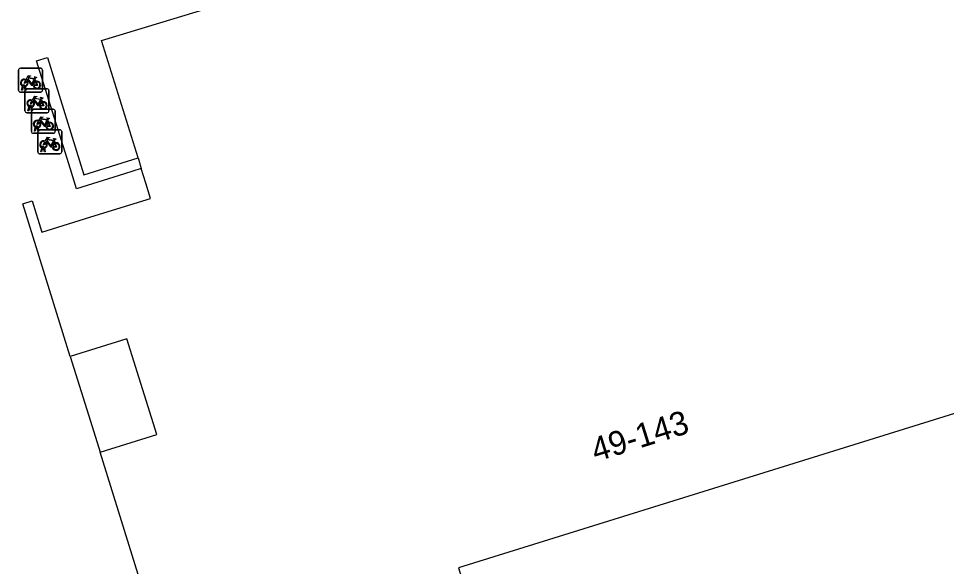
# Model space of a CAD drawing. Extents: x 161354 to 161876, y 382161 to 382804.
# Drawn here: x 161790.51 to 161829.3, y 382336.2 to 382359.11 of the extents above; entities that cross this region are included whole.
import ezdxf

# ---------------------------------------------------------------- set-up
doc = ezdxf.new("R2010")
doc.units = 0
for name, color, linetype in [('IMGEO_Fietsenrek', 7, 'Continuous'), ('IMGEO_Muur', 7, 'Continuous'), ('IMGEO_Pand', 7, 'Continuous'), ('IMGEO_Pand_nummerreeks', 7, 'Continuous'), ('IMGEO_Pand_overbouw', 7, 'Continuous')]:
    doc.layers.add(name, color=color, linetype=linetype)

msp = doc.modelspace()

# ---------------------------------------------------------------- linework, layer by layer
at = {"layer": 'IMGEO_Fietsenrek'}
for p, q in [((161790.507, 382356.108), (161790.507, 382356.949)), ((161790.507, 382356.949), (161790.507, 382356.108)), ((161790.582, 382357.033), (161791.423, 382357.033)), ((161791.423, 382357.033), (161790.582, 382357.033)), ((161791.507, 382356.958), (161791.507, 382356.117)), ((161791.507, 382356.117), (161791.507, 382356.958)), ((161791.194, 382356.582), (161791.23, 382356.487)), ((161790.634, 382356.117), (161790.673, 382356.277)), ((161790.668, 382356.117), (161790.634, 382356.117)), ((161790.703, 382356.265), (161790.668, 382356.117)), ((161790.745, 382356.289), (161790.744, 382356.293)), ((161790.786, 382356.117), (161790.752, 382356.259)), ((161790.776, 382356.3), (161790.777, 382356.293)), ((161790.784, 382356.263), (161790.819, 382356.117)), ((161790.819, 382356.117), (161790.786, 382356.117)), ((161790.85, 382356.174), (161791.691, 382356.174)), ((161791.691, 382356.174), (161790.85, 382356.174)), ((161791.432, 382356.033), (161790.591, 382356.033)), ((161790.591, 382356.033), (161791.432, 382356.033)), ((161790.775, 382355.249), (161790.775, 382356.09)), ((161790.775, 382356.09), (161790.775, 382355.249)), ((161791.775, 382356.099), (161791.775, 382355.258)), ((161791.775, 382355.258), (161791.775, 382356.099)), ((161790.902, 382355.258), (161790.941, 382355.418)), ((161790.971, 382355.406), (161790.936, 382355.258)), ((161791.013, 382355.43), (161791.012, 382355.434)), ((161791.054, 382355.258), (161791.02, 382355.4)), ((161791.044, 382355.441), (161791.045, 382355.434)), ((161791.052, 382355.404), (161791.087, 382355.258)), ((161791.462, 382355.723), (161791.498, 382355.628)), ((161791.7, 382355.174), (161790.859, 382355.174)), ((161790.859, 382355.174), (161791.7, 382355.174)), ((161790.936, 382355.258), (161790.902, 382355.258)), ((161791.042, 382354.389), (161791.042, 382355.23)), ((161791.042, 382355.23), (161791.042, 382354.389)), ((161791.087, 382355.258), (161791.054, 382355.258)), ((161791.117, 382355.314), (161791.958, 382355.314)), ((161791.958, 382355.314), (161791.117, 382355.314)), ((161792.042, 382355.239), (161792.042, 382354.398)), ((161792.042, 382354.398), (161792.042, 382355.239)), ((161791.28, 382354.57), (161791.279, 382354.574)), ((161791.311, 382354.581), (161791.312, 382354.574)), ((161791.729, 382354.863), (161791.765, 382354.768)), ((161791.967, 382354.314), (161791.126, 382354.314)), ((161791.126, 382354.314), (161791.967, 382354.314)), ((161791.169, 382354.398), (161791.208, 382354.558)), ((161791.203, 382354.398), (161791.169, 382354.398)), ((161791.238, 382354.546), (161791.203, 382354.398)), ((161791.321, 382354.398), (161791.287, 382354.54)), ((161791.31, 382353.53), (161791.31, 382354.371)), ((161791.31, 382354.371), (161791.31, 382353.53)), ((161791.319, 382354.544), (161791.354, 382354.398)), ((161791.354, 382354.398), (161791.321, 382354.398)), ((161791.385, 382354.455), (161792.226, 382354.455)), ((161792.226, 382354.455), (161791.385, 382354.455)), ((161792.31, 382354.38), (161792.31, 382353.539)), ((161792.31, 382353.539), (161792.31, 382354.38)), ((161791.997, 382354.004), (161792.033, 382353.909)), ((161792.235, 382353.455), (161791.394, 382353.455)), ((161791.394, 382353.455), (161792.235, 382353.455)), ((161791.437, 382353.539), (161791.476, 382353.699)), ((161791.471, 382353.539), (161791.437, 382353.539)), ((161791.506, 382353.687), (161791.471, 382353.539)), ((161791.548, 382353.711), (161791.547, 382353.715)), ((161791.589, 382353.539), (161791.555, 382353.681)), ((161791.579, 382353.722), (161791.58, 382353.715)), ((161791.587, 382353.685), (161791.622, 382353.539)), ((161791.622, 382353.539), (161791.589, 382353.539))]:
    msp.add_line(p, q, dxfattribs=at)
for points in [[(161790.841, 382356.507), (161790.789, 382356.417), (161790.749, 382356.392), (161790.75, 382356.439), (161790.805, 382356.533)], [(161790.82, 382356.559), (161790.915, 382356.723), (161791.001, 382356.709), (161791.003, 382356.7), (161790.947, 382356.689), (161790.92, 382356.644), (161791.176, 382356.603)], [(161791.116, 382356.315), (161791.066, 382356.315), (161790.875, 382356.566), (161790.856, 382356.534)], [(161791.163, 382356.578), (161790.906, 382356.619), (161790.889, 382356.59), (161791.056, 382356.37), (161791.163, 382356.578)], [(161791.211, 382356.48), (161791.181, 382356.557), (161791.072, 382356.339), (161791.115, 382356.339)], [(161791.176, 382356.603), (161791.201, 382356.652), (161791.195, 382356.656), (161791.172, 382356.66), (161791.16, 382356.667), (161791.159, 382356.67), (161791.161, 382356.675), (161791.256, 382356.66), (161791.258, 382356.65), (161791.248, 382356.637), (161791.236, 382356.631), (161791.222, 382356.637), (161791.194, 382356.582)], [(161791.145, 382356.339), (161791.265, 382356.338), (161791.221, 382356.452)], [(161791.241, 382356.459), (161791.296, 382356.314), (161791.146, 382356.314)], [(161791.088, 382355.7), (161791.183, 382355.864), (161791.269, 382355.85), (161791.271, 382355.841), (161791.215, 382355.83), (161791.188, 382355.785), (161791.444, 382355.744)], [(161791.431, 382355.719), (161791.174, 382355.76), (161791.157, 382355.731), (161791.324, 382355.511), (161791.431, 382355.719)], [(161791.444, 382355.744), (161791.469, 382355.793), (161791.463, 382355.797), (161791.44, 382355.801), (161791.428, 382355.808), (161791.427, 382355.811), (161791.429, 382355.816), (161791.524, 382355.801), (161791.526, 382355.791), (161791.516, 382355.778), (161791.504, 382355.772), (161791.49, 382355.778), (161791.462, 382355.723)], [(161791.109, 382355.648), (161791.057, 382355.558), (161791.017, 382355.533), (161791.018, 382355.58), (161791.073, 382355.674)], [(161791.384, 382355.456), (161791.334, 382355.456), (161791.143, 382355.707), (161791.124, 382355.675)], [(161791.479, 382355.621), (161791.449, 382355.698), (161791.34, 382355.48), (161791.383, 382355.48)], [(161791.413, 382355.48), (161791.533, 382355.479), (161791.489, 382355.593)], [(161791.509, 382355.6), (161791.564, 382355.455), (161791.414, 382355.455)], [(161791.355, 382354.84), (161791.45, 382355.004), (161791.536, 382354.99), (161791.538, 382354.981), (161791.482, 382354.97), (161791.455, 382354.925), (161791.711, 382354.884)], [(161791.711, 382354.884), (161791.736, 382354.933), (161791.73, 382354.937), (161791.707, 382354.941), (161791.695, 382354.948), (161791.694, 382354.951), (161791.696, 382354.956), (161791.791, 382354.941), (161791.793, 382354.931), (161791.783, 382354.918), (161791.771, 382354.912), (161791.757, 382354.918), (161791.729, 382354.863)], [(161791.376, 382354.788), (161791.324, 382354.698), (161791.284, 382354.673), (161791.285, 382354.72), (161791.34, 382354.814)], [(161791.651, 382354.596), (161791.601, 382354.596), (161791.41, 382354.847), (161791.391, 382354.815)], [(161791.698, 382354.859), (161791.441, 382354.9), (161791.424, 382354.871), (161791.591, 382354.651), (161791.698, 382354.859)], [(161791.746, 382354.761), (161791.716, 382354.838), (161791.607, 382354.62), (161791.65, 382354.62)], [(161791.68, 382354.62), (161791.8, 382354.619), (161791.756, 382354.733)], [(161791.776, 382354.74), (161791.831, 382354.595), (161791.681, 382354.595)], [(161791.644, 382353.929), (161791.592, 382353.839), (161791.552, 382353.814), (161791.553, 382353.861), (161791.608, 382353.955)], [(161791.623, 382353.981), (161791.718, 382354.145), (161791.804, 382354.131), (161791.806, 382354.122), (161791.75, 382354.111), (161791.723, 382354.066), (161791.979, 382354.025)], [(161791.919, 382353.737), (161791.869, 382353.737), (161791.678, 382353.988), (161791.659, 382353.956)], [(161791.966, 382354), (161791.709, 382354.041), (161791.692, 382354.012), (161791.859, 382353.792), (161791.966, 382354)], [(161792.014, 382353.902), (161791.984, 382353.979), (161791.875, 382353.761), (161791.918, 382353.761)], [(161791.948, 382353.761), (161792.068, 382353.76), (161792.024, 382353.874)], [(161792.044, 382353.881), (161792.099, 382353.736), (161791.949, 382353.736)], [(161791.979, 382354.025), (161792.004, 382354.074), (161791.998, 382354.078), (161791.975, 382354.082), (161791.963, 382354.089), (161791.962, 382354.092), (161791.964, 382354.097), (161792.059, 382354.082), (161792.061, 382354.072), (161792.051, 382354.059), (161792.039, 382354.053), (161792.025, 382354.059), (161791.997, 382354.004)]]:
    msp.add_lwpolyline(points, dxfattribs=at)
for centre, radius, start, end in [((161790.585, 382356.955), 0.0779, 92.4484, 184.2845), ((161790.585, 382356.955), 0.0779, 92.4484, 184.2845), ((161791.429, 382356.955), 0.0779, 2.4484, 94.2845), ((161791.429, 382356.955), 0.0779, 2.4484, 94.2845), ((161790.747, 382356.418), 0.159, 62.6766, 242.1369), ((161790.747, 382356.418), 0.129, 63.3192, 238.903), ((161790.747, 382356.418), 0.129, 283.6043, 43.4302), ((161790.747, 382356.418), 0.159, 283.5766, 46.6042), ((161790.727, 382356.289), 0.0499, 12.8025, 158.6934), ((161790.747, 382356.418), 0.159, 253.9967, 271.7867), ((161790.727, 382356.289), 0.0174, 12.8025, 163.4502), ((161790.747, 382356.418), 0.129, 253.415, 269.0204), ((161790.853, 382356.096), 0.0779, 92.4484, 184.2845), ((161790.853, 382356.096), 0.0779, 92.4484, 184.2845), ((161791.274, 382356.334), 0.159, 113.3408, 178.3217), ((161791.274, 382356.334), 0.159, 187.0065, 105.7708), ((161791.274, 382356.334), 0.129, 113.923, 177.9556), ((161791.274, 382356.334), 0.129, 188.6715, 104.5883), ((161791.429, 382356.111), 0.0779, 272.4484, 4.2845), ((161791.429, 382356.111), 0.0779, 272.4484, 4.2845), ((161791.697, 382356.096), 0.0779, 2.4484, 94.2845), ((161791.697, 382356.096), 0.0779, 2.4484, 94.2845), ((161790.585, 382356.111), 0.0779, 182.4484, 274.2845), ((161790.585, 382356.111), 0.0779, 182.4484, 274.2845), ((161791.015, 382355.559), 0.159, 62.6766, 242.1369), ((161791.015, 382355.559), 0.129, 63.3192, 238.903), ((161790.995, 382355.43), 0.0499, 12.8025, 158.6934), ((161791.015, 382355.559), 0.159, 253.9967, 271.7867), ((161790.995, 382355.43), 0.0174, 12.8025, 163.4502), ((161791.015, 382355.559), 0.129, 253.415, 269.0204), ((161791.015, 382355.559), 0.129, 283.6043, 43.4302), ((161791.015, 382355.559), 0.159, 283.5766, 46.6042), ((161791.542, 382355.475), 0.159, 113.3408, 178.3217), ((161791.542, 382355.475), 0.159, 187.0065, 105.7708), ((161791.542, 382355.475), 0.129, 113.923, 177.9556), ((161791.542, 382355.475), 0.129, 188.6715, 104.5883), ((161790.853, 382355.252), 0.0779, 182.4484, 274.2845), ((161790.853, 382355.252), 0.0779, 182.4484, 274.2845), ((161791.12, 382355.236), 0.0779, 92.4484, 184.2845), ((161791.12, 382355.236), 0.0779, 92.4484, 184.2845), ((161791.697, 382355.252), 0.0779, 272.4484, 4.2845), ((161791.697, 382355.252), 0.0779, 272.4484, 4.2845), ((161791.964, 382355.236), 0.0779, 2.4484, 94.2845), ((161791.964, 382355.236), 0.0779, 2.4484, 94.2845), ((161791.282, 382354.699), 0.159, 62.6766, 242.1369), ((161791.282, 382354.699), 0.129, 63.3192, 238.903), ((161791.262, 382354.57), 0.0499, 12.8025, 158.6934), ((161791.262, 382354.57), 0.0174, 12.8025, 163.4502), ((161791.282, 382354.699), 0.129, 253.415, 269.0204), ((161791.282, 382354.699), 0.129, 283.6043, 43.4302), ((161791.282, 382354.699), 0.159, 283.5766, 46.6042), ((161791.809, 382354.615), 0.159, 113.3408, 178.3217), ((161791.809, 382354.615), 0.159, 187.0065, 105.7708), ((161791.809, 382354.615), 0.129, 113.923, 177.9556), ((161791.809, 382354.615), 0.129, 188.6715, 104.5883), ((161791.12, 382354.392), 0.0779, 182.4484, 274.2845), ((161791.12, 382354.392), 0.0779, 182.4484, 274.2845), ((161791.282, 382354.699), 0.159, 253.9967, 271.7867), ((161791.388, 382354.377), 0.0779, 92.4484, 184.2845), ((161791.388, 382354.377), 0.0779, 92.4484, 184.2845), ((161791.964, 382354.392), 0.0779, 272.4484, 4.2845), ((161791.964, 382354.392), 0.0779, 272.4484, 4.2845), ((161792.232, 382354.377), 0.0779, 2.4484, 94.2845), ((161792.232, 382354.377), 0.0779, 2.4484, 94.2845), ((161791.55, 382353.84), 0.159, 62.6766, 242.1369), ((161791.55, 382353.84), 0.129, 63.3192, 238.903), ((161791.55, 382353.84), 0.129, 283.6043, 43.4302), ((161791.55, 382353.84), 0.159, 283.5766, 46.6042), ((161792.077, 382353.756), 0.159, 113.3408, 178.3217), ((161792.077, 382353.756), 0.159, 187.0065, 105.7708), ((161792.077, 382353.756), 0.129, 113.923, 177.9556), ((161792.077, 382353.756), 0.129, 188.6715, 104.5883), ((161791.388, 382353.533), 0.0779, 182.4484, 274.2845), ((161791.388, 382353.533), 0.0779, 182.4484, 274.2845), ((161791.53, 382353.711), 0.0499, 12.8025, 158.6934), ((161791.55, 382353.84), 0.159, 253.9967, 271.7867), ((161791.53, 382353.711), 0.0174, 12.8025, 163.4502), ((161791.55, 382353.84), 0.129, 253.415, 269.0204), ((161792.232, 382353.533), 0.0779, 272.4484, 4.2845), ((161792.232, 382353.533), 0.0779, 272.4484, 4.2845)]:
    msp.add_arc(centre, radius, start, end, dxfattribs=at)
at = {"layer": 'IMGEO_Muur'}
msp.add_lwpolyline([(161795.639, 382352.84), (161794.935, 382352.621), (161792.927, 382351.996), (161792.674, 382352.809), (161791.263, 382357.343), (161791.712, 382357.483), (161793.239, 382352.575), (161795.502, 382353.279)], dxfattribs=at)
at = {"layer": 'IMGEO_Pand'}
for points in [[(161842.189, 382365.055), (161837.093, 382363.468), (161838.393, 382359.291), (161836.108, 382358.579), (161840.073, 382345.844), (161808.898, 382336.138), (161809.407, 382334.506), (161806.959, 382333.743), (161806.882, 382333.99), (161797.046, 382330.928)], [(161795.502, 382353.279), (161793.974, 382358.187), (161798.853, 382359.671)], [(161795.502, 382353.279), (161795.639, 382352.84)], [(161797.046, 382330.928), (161793.916, 382340.982), (161796.284, 382341.719), (161795.038, 382345.72), (161792.67, 382344.983), (161790.685, 382351.361), (161791.076, 382351.483), (161791.483, 382350.174), (161793.71, 382350.868), (161796.028, 382351.589), (161795.831, 382352.223), (161795.639, 382352.84)]]:
    msp.add_lwpolyline(points, dxfattribs=at)
at = {"layer": 'IMGEO_Pand_overbouw'}
msp.add_lwpolyline([(161795.038, 382345.72), (161792.67, 382344.983), (161793.583, 382342.049), (161793.916, 382340.982), (161796.284, 382341.719)], close=True, dxfattribs=at)

# ---------------------------------------------------------------- texts
at = {"layer": 'IMGEO_Pand_nummerreeks'}
msp.add_text('49-143', height=1, rotation=17.2919, dxfattribs=at).set_placement((161814.637, 382340.564))

doc.saveas('drawing.dxf')
